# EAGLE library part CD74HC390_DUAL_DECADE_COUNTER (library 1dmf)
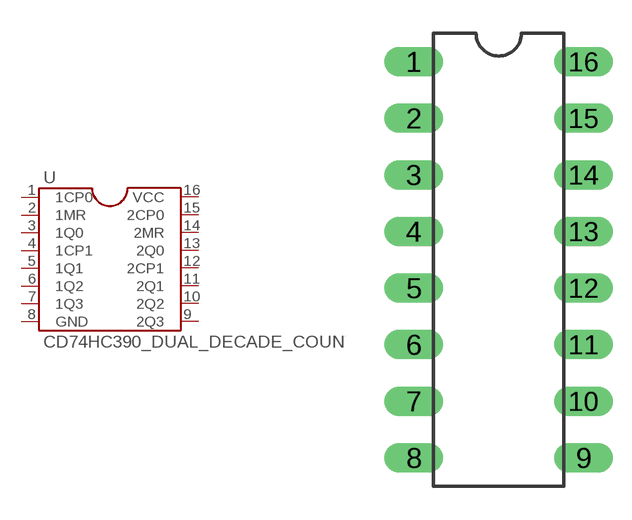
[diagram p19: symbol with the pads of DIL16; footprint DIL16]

Designator prefix -

## CD74HC390_DUAL_DECADE_COUNTER  [DIL16]
1  1CP0  pas
2  1MR  pas
3  1Q0  pas
4  1CP1  pas
5  1Q1  pas
6  1Q2  pas
7  1Q3  pas
8  GND  pas
9  2Q3  pas
10  2Q2  pas
11  2Q1  pas
12  2CP1  pas
13  2Q0  pas
14  2MR  pas
15  2CP0  pas
16  VCC  pas

## Footprint DIL16 (pad centres in mm)
drill 0.813 long: 1 -3.81,7.62; 2 -3.81,5.08; 3 -3.81,2.54; 4 -3.81,0; 5 -3.81,-2.54; 6 -3.81,-5.08; 7 -3.81,-7.62; 8 -3.81,-10.16; 9 3.81,-10.16; 10 3.81,-7.62; 11 3.81,-5.08; 12 3.81,-2.54; 13 3.81,0; 14 3.81,2.54; 15 3.81,5.08; 16 3.81,7.62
